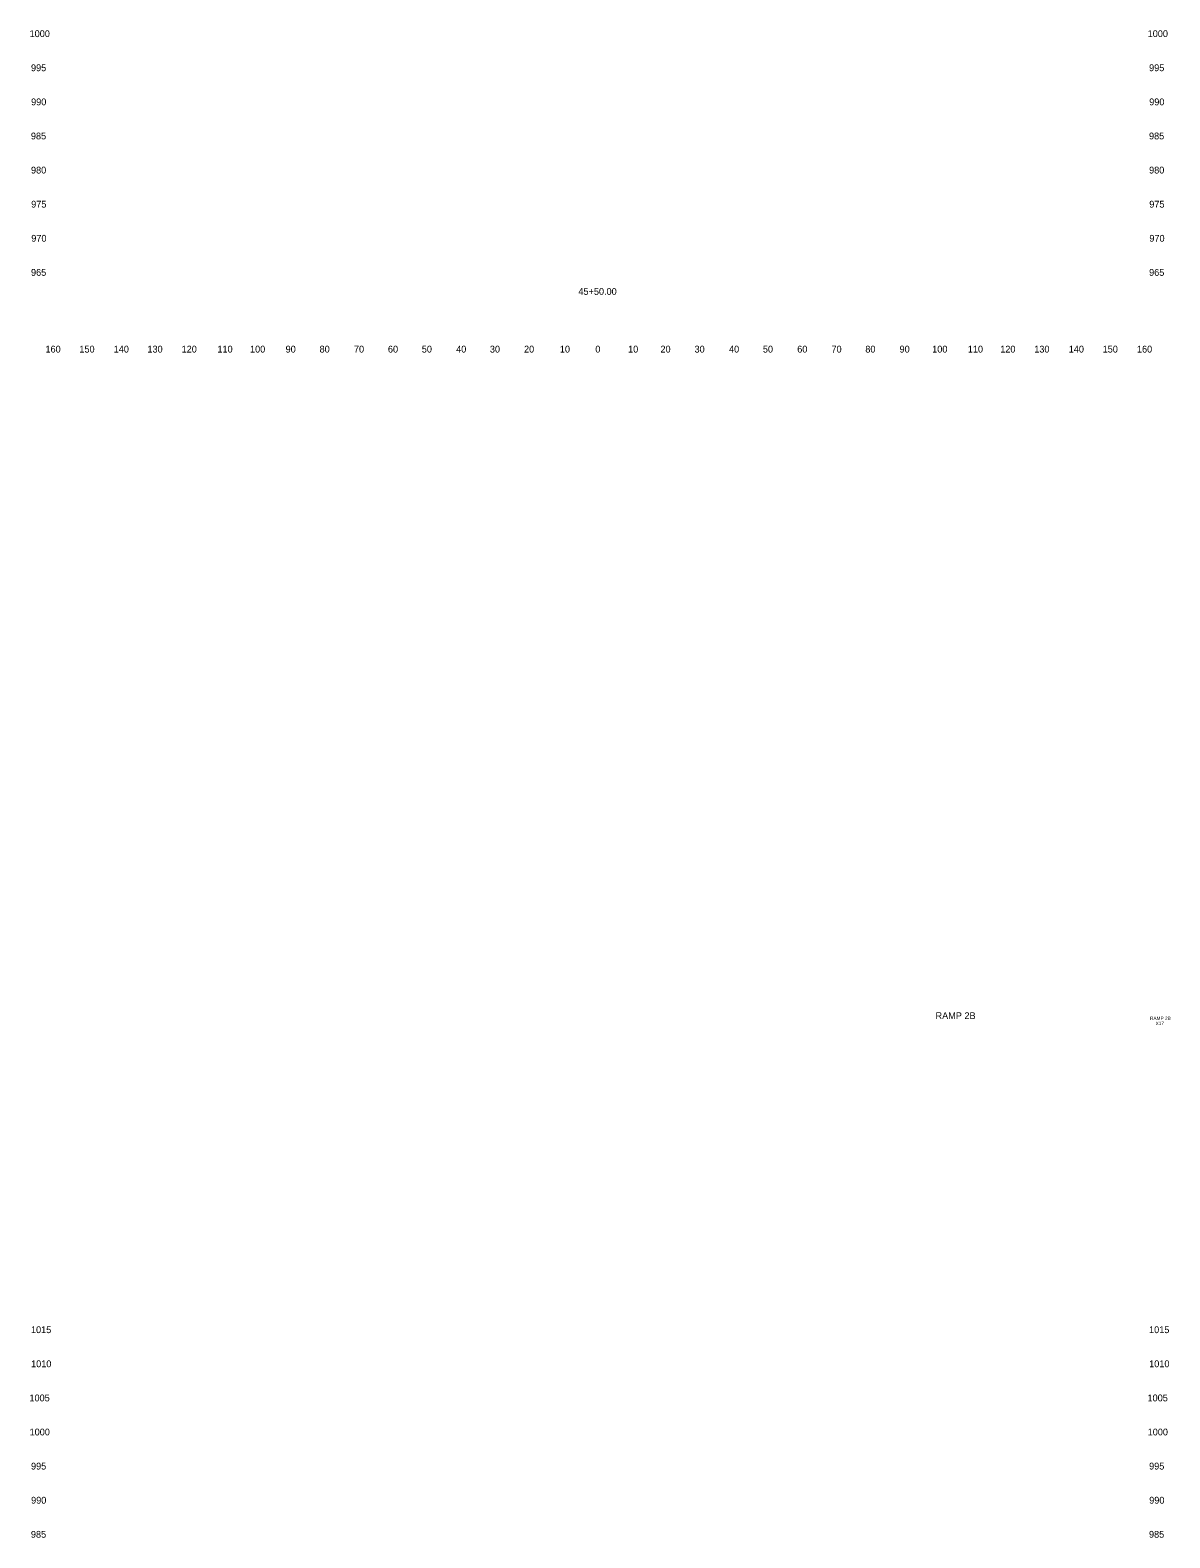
# Model space of a CAD drawing. Extents: x 4994 to 6358, y 4997 to 8804.
# Drawn here: x 5508.6 to 5842.7, y 7450 to 7892 of the extents above; entities that cross this region are included whole.
import ezdxf

# ---------------------------------------------------------------- set-up
doc = ezdxf.new("R2010")
doc.units = 0
for name, color, linetype in [('RD_SHT_ID', 7, 'Continuous'), ('RD_XS_TX_Offset', 7, 'Continuous'), ('RD_XS_TX_Station', 7, 'Continuous')]:
    doc.layers.add(name, color=color, linetype=linetype)

msp = doc.modelspace()

# ---------------------------------------------------------------- texts
at = {"layer": 'RD_SHT_ID'}
for s, height, p in [('RAMP 2B', 2, (5774.05, 7602.06)), ('RAMP 2B', 1, (5836.94, 7601.8)), ('X17', 1, (5838.57, 7600.3))]:
    msp.add_text(s, height=height, dxfattribs=at).set_placement(p)
at = {"layer": 'RD_XS_TX_Offset'}
for s, p in [('1000', (5508.44, 7890)), ('1000', (5836.24, 7890)), ('995', (5508.86, 7880)), ('995', (5836.66, 7880)), ('990', (5508.89, 7870)), ('990', (5836.69, 7870)), ('985', (5508.83, 7860)), ('985', (5836.63, 7860)), ('980', (5508.86, 7850)), ('980', (5836.66, 7850)), ('975', (5508.91, 7840)), ('975', (5836.71, 7840)), ('970', (5508.94, 7830)), ('970', (5836.74, 7830)), ('965', (5508.86, 7820)), ('965', (5836.66, 7820)), ('160', (5513.1, 7797.5)), ('150', (5523.04, 7797.5)), ('140', (5533.1, 7797.5)), ('130', (5542.99, 7797.5)), ('120', (5553.01, 7797.5)), ('110', (5563.51, 7797.5)), ('100', (5573.07, 7797.5)), ('90', (5583.5, 7797.5)), ('80', (5593.46, 7797.5)), ('70', (5603.54, 7797.5)), ('60', (5613.5, 7797.5)), ('50', (5623.43, 7797.5)), ('40', (5633.5, 7797.5)), ('30', (5643.39, 7797.5)), ('20', (5653.4, 7797.5)), ('10', (5663.91, 7797.5)), ('0', (5674.3, 7797.5)), ('0', (5674.3, 7797.5)), ('10', (5683.91, 7797.5)), ('20', (5693.4, 7797.5)), ('30', (5703.39, 7797.5)), ('40', (5713.5, 7797.5)), ('50', (5723.43, 7797.5)), ('60', (5733.5, 7797.5)), ('70', (5743.54, 7797.5)), ('80', (5753.46, 7797.5)), ('90', (5763.5, 7797.5)), ('100', (5773.07, 7797.5)), ('110', (5783.51, 7797.5)), ('120', (5793.01, 7797.5)), ('130', (5802.99, 7797.5)), ('140', (5813.1, 7797.5)), ('150', (5823.04, 7797.5)), ('160', (5833.1, 7797.5)), ('1015', (5508.85, 7510)), ('1015', (5836.65, 7510)), ('1010', (5508.88, 7500)), ('1010', (5836.68, 7500)), ('1005', (5508.4, 7490)), ('1005', (5836.2, 7490)), ('1000', (5508.44, 7480)), ('1000', (5836.24, 7480)), ('995', (5508.86, 7470)), ('995', (5836.66, 7470)), ('990', (5508.89, 7460)), ('990', (5836.69, 7460)), ('985', (5508.83, 7450)), ('985', (5836.63, 7450))]:
    msp.add_text(s, height=2, dxfattribs=at).set_placement(p)
at = {"layer": 'RD_XS_TX_Station'}
msp.add_text('45+50.00', height=2, dxfattribs=at).set_placement((5669.35, 7814.41))

doc.saveas('drawing.dxf')
